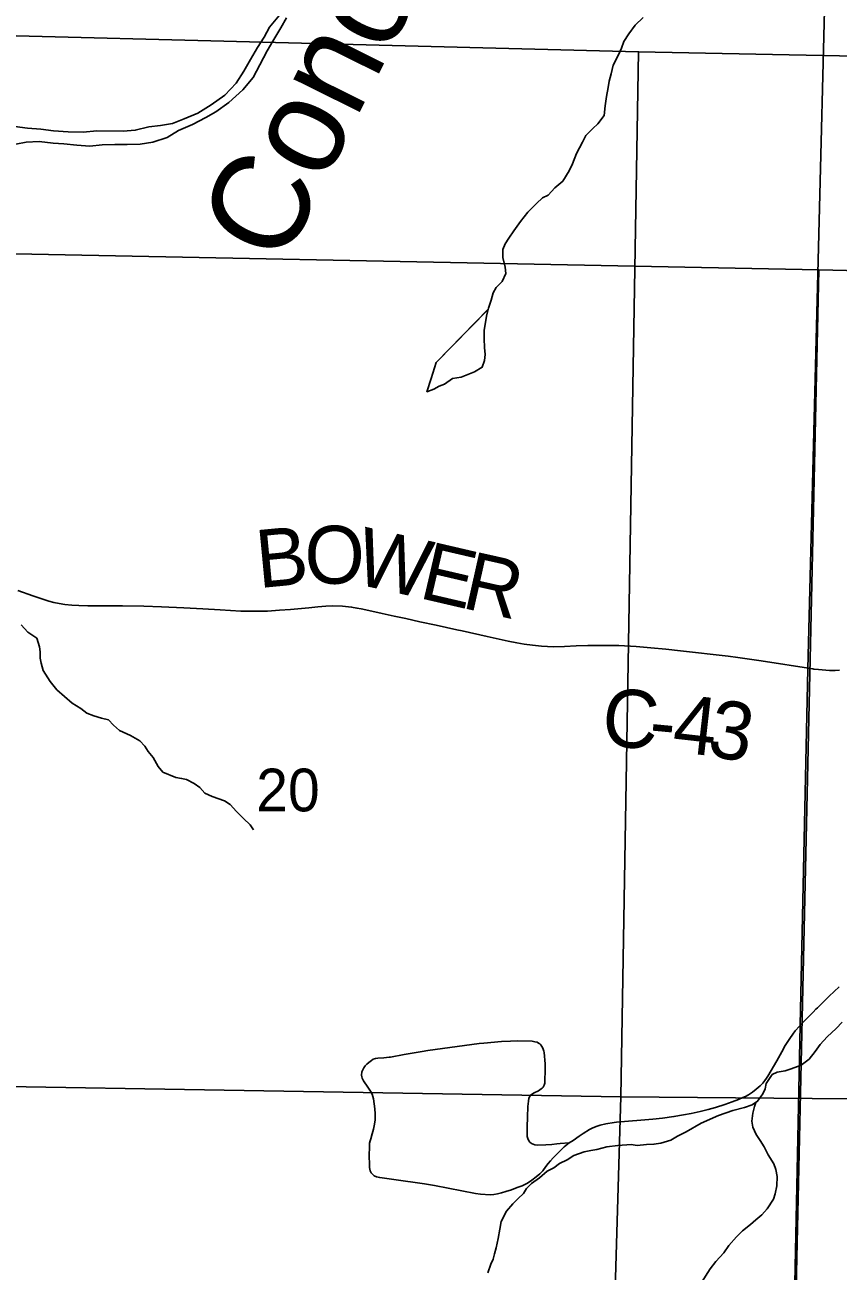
# Model space of a CAD drawing. Extents: x -19.9 to 41.9, y 0 to 32.3.
# Drawn here: x 6.268 to 7.065, y 15.733 to 16.956 of the extents above; entities that cross this region are included whole.
import ezdxf

# ---------------------------------------------------------------- set-up
doc = ezdxf.new("R2010")
doc.units = 0
for name, color, linetype in [('GM_X_Corporation', 7, 'Continuous'), ('GM_X_County_Road', 7, 'Continuous'), ('GM_X_County_Road_Text', 7, 'Continuous'), ('GM_X_Major_River', 7, 'Continuous'), ('GM_X_Major_River_Text', 7, 'Continuous'), ('GM_X_Minor_River', 7, 'Continuous'), ('GM_X_Section', 7, 'Continuous'), ('GM_X_Section_Text', 7, 'Continuous'), ('GM_X_Township', 7, 'Continuous'), ('GM_X_Township_Road', 7, 'Continuous')]:
    doc.layers.add(name, color=color, linetype=linetype)

msp = doc.modelspace()

# ---------------------------------------------------------------- linework, layer by layer
at = {"layer": 'GM_X_Corporation'}
for points in [[(5.8519, 16.9554), (6.8696, 16.9292), (6.8522, 15.9041), (5.8404, 15.9209)], [(6.8696, 16.9292), (7.8883, 16.9088), (7.8659, 15.8953), (6.8522, 15.9041)], [(6.8522, 15.9041), (6.8226, 14.894), (5.8188, 14.9036), (5.8404, 15.9209)], [(7.8659, 15.8953), (7.8436, 14.8739), (6.8226, 14.894), (6.8522, 15.9041)]]:
    msp.add_lwpolyline(points, close=True, dxfattribs=at)
at = {"layer": 'GM_X_County_Road'}
for points in [[(6.2608, 16.4008), (6.2755, 16.3954), (6.2842, 16.3925), (6.291, 16.3904), (6.296, 16.3891), (6.3011, 16.388), (6.3067, 16.3871), (6.3138, 16.3864), (6.3206, 16.386), (6.3294, 16.3858), (6.3635, 16.3857), (6.3843, 16.3852), (6.4018, 16.3847), (6.4235, 16.3838), (6.4421, 16.3829), (6.4593, 16.3819), (6.4796, 16.3806), (6.4853, 16.3804), (6.5055, 16.3806), (6.5175, 16.3813), (6.5282, 16.3821), (6.5463, 16.3838), (6.5549, 16.3847), (6.5628, 16.3853), (6.5691, 16.3856), (6.5792, 16.3854), (6.5822, 16.3851), (6.5881, 16.3844), (6.5934, 16.3834), (6.5976, 16.3826), (6.6078, 16.3804), (6.618, 16.3782), (6.6299, 16.3755), (6.6412, 16.3731), (6.655, 16.37), (6.6709, 16.3666), (6.6912, 16.3622), (6.6966, 16.361), (6.721, 16.3557), (6.7418, 16.3511), (6.7502, 16.3494), (6.7574, 16.3481), (6.7656, 16.347), (6.7744, 16.3461), (6.7802, 16.3457), (6.7859, 16.3456), (6.7969, 16.3459), (6.8083, 16.3463), (6.8199, 16.3467), (6.8295, 16.3469), (6.841, 16.3469), (6.8501, 16.3467), (6.8671, 16.3457), (6.8816, 16.3446), (6.8964, 16.3432), (6.9107, 16.3417), (6.9575, 16.3362), (6.967, 16.335), (6.9898, 16.3316), (7.0406, 16.3238), (7.0415, 16.3237)], [(7.0415, 16.3237), (7.046, 16.3232), (7.0569, 16.3224), (7.0624, 16.3223), (7.0667, 16.3225)]]:
    msp.add_lwpolyline(points, dxfattribs=at)
at = {"layer": 'GM_X_Major_River'}
for points in [[(6.5173, 16.9652), (6.5076, 16.9533), (6.5024, 16.9434), (6.4957, 16.9334), (6.489, 16.9216), (6.4823, 16.9101), (6.4748, 16.8983), (6.4636, 16.8867), (6.4504, 16.8771), (6.4372, 16.869), (6.424, 16.8635), (6.4123, 16.8588), (6.4005, 16.8568), (6.3891, 16.8555), (6.3759, 16.8523), (6.3641, 16.8514), (6.3383, 16.8518), (6.3247, 16.8502), (6.3102, 16.8507), (6.2958, 16.8517), (6.2832, 16.8534), (6.2703, 16.8544), (6.2578, 16.8558)], [(6.2587, 16.8387), (6.269, 16.8404), (6.2815, 16.8413), (6.2955, 16.8396), (6.3058, 16.8389), (6.3187, 16.8376), (6.3313, 16.8366), (6.3434, 16.8379), (6.3559, 16.8384), (6.3681, 16.8382), (6.3806, 16.8387), (6.3931, 16.8407), (6.4071, 16.8451), (6.4184, 16.852), (6.432, 16.8579), (6.4452, 16.8649), (6.455, 16.8703), (6.4678, 16.8796), (6.4814, 16.8919), (6.4915, 16.9041), (6.4981, 16.9164), (6.5052, 16.9301), (6.5108, 16.9397), (6.5186, 16.9527), (6.5242, 16.9626)]]:
    msp.add_lwpolyline(points, dxfattribs=at)
at = {"layer": 'GM_X_Minor_River'}
for points in [[(6.874, 16.9629), (6.8662, 16.9552), (6.8599, 16.9467), (6.8551, 16.9394), (6.8529, 16.9329), (6.8496, 16.9256), (6.8448, 16.916), (6.8427, 16.9076), (6.8409, 16.9003), (6.8398, 16.8942), (6.8381, 16.8854), (6.837, 16.8763), (6.8357, 16.8667), (6.8297, 16.8586), (6.8249, 16.854), (6.8178, 16.847), (6.8145, 16.8405), (6.8086, 16.8294), (6.8049, 16.8194), (6.8016, 16.8125), (6.7953, 16.8022), (6.7875, 16.7956), (6.7808, 16.7886), (6.7755, 16.7859), (6.7695, 16.7804), (6.7609, 16.7719), (6.7539, 16.7627), (6.7472, 16.7535), (6.7424, 16.7465), (6.7387, 16.7408), (6.7365, 16.7354), (6.7366, 16.7274), (6.7386, 16.7179), (6.7395, 16.7118), (6.7358, 16.7038), (6.7298, 16.698), (6.7269, 16.6926), (6.7251, 16.6857), (6.7225, 16.6777), (6.7204, 16.6697), (6.7183, 16.6559), (6.7181, 16.6475), (6.7186, 16.6392), (6.719, 16.6323), (6.7184, 16.6262), (6.7162, 16.6197), (6.7087, 16.6154), (6.6955, 16.6099), (6.6872, 16.6086), (6.6793, 16.6032), (6.674, 16.6012), (6.6688, 16.5981), (6.662, 16.5957), (6.666, 16.6087), (6.6711, 16.6244), (6.7218, 16.6762)], [(6.662, 16.5957), (6.6688, 16.5981), (6.674, 16.6012), (6.6793, 16.6032), (6.6872, 16.6086), (6.6955, 16.6099), (6.7087, 16.6154), (6.7162, 16.6197), (6.7184, 16.6262), (6.719, 16.6323), (6.7186, 16.6392), (6.7181, 16.6475), (6.7183, 16.6559), (6.7204, 16.6697), (6.7222, 16.6766)], [(6.7222, 16.6766), (6.6711, 16.6244), (6.666, 16.6087), (6.662, 16.5957)], [(6.264, 16.367), (6.2705, 16.3598), (6.2793, 16.3539), (6.2821, 16.3455), (6.2826, 16.3406), (6.2826, 16.3345), (6.2835, 16.3296), (6.2855, 16.3224), (6.2924, 16.3114), (6.299, 16.3032), (6.314, 16.2901), (6.3224, 16.2849), (6.3285, 16.2804), (6.3353, 16.2778), (6.3429, 16.2756), (6.3498, 16.2738), (6.3544, 16.2686), (6.3605, 16.2633), (6.3712, 16.2586), (6.3804, 16.2534), (6.3854, 16.2481), (6.3885, 16.2428), (6.3935, 16.2368), (6.3985, 16.2281), (6.4031, 16.2225), (6.4157, 16.2173), (6.4214, 16.2163), (6.4263, 16.2152), (6.4336, 16.2115), (6.4393, 16.2074), (6.4443, 16.2018), (6.4512, 16.1985), (6.4634, 16.1945), (6.4691, 16.1907), (6.4753, 16.184), (6.4822, 16.1772), (6.4887, 16.1709), (6.4918, 16.166)], [(7.0693, 15.9771), (7.0633, 15.9709), (7.0547, 15.9628), (7.0476, 15.9555), (7.0428, 15.9485), (7.0369, 15.9408), (7.029, 15.935), (7.0192, 15.9314), (7.0135, 15.9294), (7.0056, 15.9282), (7.0007, 15.9258), (6.9948, 15.917), (6.9937, 15.912), (6.9915, 15.907), (6.9863, 15.8997), (6.9811, 15.8962), (6.9736, 15.8934), (6.9622, 15.8906), (6.9479, 15.8858), (6.931, 15.8783), (6.9163, 15.8697), (6.9077, 15.8654), (6.9013, 15.8615), (6.8915, 15.8587), (6.8847, 15.8575), (6.8775, 15.8573), (6.8681, 15.8564), (6.8624, 15.8571), (6.8492, 15.8562), (6.8386, 15.8548), (6.8288, 15.8524), (6.8227, 15.8512), (6.8163, 15.8499), (6.8061, 15.8464), (6.7994, 15.8421), (6.7919, 15.8385), (6.7866, 15.8343), (6.7799, 15.8311), (6.7724, 15.8245), (6.7645, 15.8191), (6.7597, 15.8141), (6.7567, 15.8091), (6.7515, 15.8044), (6.7462, 15.799), (6.7399, 15.7917), (6.7348, 15.7817), (6.7334, 15.7741), (6.732, 15.7649), (6.7298, 15.7558), (6.7284, 15.75), (6.727, 15.7447), (6.7248, 15.7397), (6.7219, 15.7313)], [(6.9846, 15.8986), (6.9834, 15.8944), (6.9816, 15.8879), (6.9806, 15.8802), (6.9818, 15.8742), (6.9849, 15.867), (6.9888, 15.8613), (6.9927, 15.8549), (6.9966, 15.847), (7.0024, 15.8383), (7.0043, 15.8326), (7.0056, 15.8258), (7.0053, 15.8167), (7.0036, 15.809), (7.0021, 15.8037), (6.9958, 15.794), (6.9906, 15.7883), (6.9846, 15.7832), (6.9794, 15.7786), (6.9715, 15.7724), (6.9656, 15.7666), (6.9581, 15.7581), (6.9533, 15.7508), (6.9455, 15.7423), (6.9399, 15.7353), (6.9314, 15.7219)]]:
    msp.add_lwpolyline(points, dxfattribs=at)
at = {"layer": 'GM_X_Section'}
for points in [[(6.0276, 16.7357), (7.0463, 16.7153), (7.0239, 15.7019), (6.0103, 15.7106)], [(8.0651, 16.6907), (8.0435, 15.6754), (7.0239, 15.7019), (7.0463, 16.7153)]]:
    msp.add_lwpolyline(points, close=True, dxfattribs=at)
at = {"layer": 'GM_X_Township'}
for p, q in [((7.0592, 17.259), (7.0356, 16.3239)), ((7.0356, 16.3239), (7.0282, 15.9744)), ((7.0282, 15.9744), (7.012, 15.2123))]:
    msp.add_line(p, q, dxfattribs=at)
at = {"layer": 'GM_X_Township_Road'}
for points in [[(7.0436, 15.9899), (7.045, 15.9913), (7.0564, 16.0026), (7.0663, 16.012)], [(7.0309, 15.9771), (7.0368, 15.983), (7.0408, 15.9871), (7.0436, 15.9899)], [(6.7757, 15.8315), (6.7787, 15.8356), (6.781, 15.8386), (6.7833, 15.8412), (6.7858, 15.844), (6.7894, 15.8477), (6.794, 15.8523), (6.7967, 15.8549), (6.8016, 15.8588), (6.8053, 15.8612), (6.8114, 15.8655), (6.8153, 15.868), (6.8215, 15.8718), (6.8247, 15.8735), (6.8289, 15.8751), (6.832, 15.8761), (6.8375, 15.8774), (6.8458, 15.8787), (6.8479, 15.879), (6.8835, 15.8822), (6.8931, 15.8832), (6.9043, 15.8846), (6.9136, 15.8862), (6.9213, 15.8877), (6.93, 15.8896), (6.938, 15.8916), (6.9451, 15.8936), (6.9541, 15.8965), (6.9613, 15.899), (6.9675, 15.9013), (6.972, 15.9033), (6.9744, 15.9044), (6.9773, 15.9061), (6.9814, 15.9087), (6.985, 15.9115), (6.9889, 15.9149), (6.9915, 15.9175), (6.9935, 15.9199), (6.9952, 15.9223), (6.9965, 15.9243), (7.0051, 15.9392), (7.01, 15.948), (7.0135, 15.9542), (7.0181, 15.9613), (7.0209, 15.9654), (7.0232, 15.9688), (7.0273, 15.9734), (7.0309, 15.9771)], [(6.7757, 15.8315), (6.7727, 15.8284), (6.7691, 15.8255), (6.7649, 15.8223), (6.7606, 15.8193), (6.7553, 15.8168), (6.7505, 15.8149), (6.7449, 15.8128), (6.7393, 15.8111), (6.7351, 15.8097), (6.7311, 15.8088), (6.7275, 15.8081), (6.7241, 15.8078), (6.7147, 15.8085), (6.7098, 15.8092), (6.6695, 15.817), (6.6596, 15.8186), (6.6297, 15.8229), (6.6158, 15.8248), (6.6126, 15.8255), (6.6104, 15.8266), (6.6085, 15.828), (6.6073, 15.8294), (6.6063, 15.8313), (6.6061, 15.8329), (6.6058, 15.8347), (6.6056, 15.8388), (6.6055, 15.8447), (6.6056, 15.8565), (6.6058, 15.8586), (6.6063, 15.8609), (6.6069, 15.8628), (6.6083, 15.8677), (6.6097, 15.8723), (6.6106, 15.8771), (6.6112, 15.8814), (6.6113, 15.8872), (6.6109, 15.8921), (6.6095, 15.902), (6.6082, 15.9066), (6.6067, 15.9097), (6.6035, 15.9146), (6.6005, 15.9186), (6.5999, 15.9196), (6.5985, 15.9224), (6.5981, 15.9237), (6.5978, 15.9253), (6.5981, 15.9284), (6.5994, 15.9313), (6.6001, 15.9325), (6.6015, 15.9343), (6.603, 15.936), (6.605, 15.9378), (6.6076, 15.9398), (6.6094, 15.941), (6.6117, 15.9415), (6.614, 15.942), (6.6196, 15.9424), (6.6249, 15.9428), (6.6264, 15.943), (6.6396, 15.9454), (6.6574, 15.9486), (6.663, 15.9494), (6.7133, 15.9563), (6.7177, 15.9568), (6.7351, 15.9582), (6.7439, 15.9587), (6.7505, 15.9588), (6.7652, 15.9586), (6.7677, 15.9581), (6.77, 15.9575), (6.7716, 15.9567), (6.7727, 15.9559), (6.7736, 15.9551), (6.7748, 15.9535), (6.7758, 15.9516), (6.7767, 15.9489), (6.777, 15.9476), (6.7779, 15.9365), (6.7781, 15.9323), (6.7778, 15.9175), (6.7769, 15.9154), (6.7759, 15.9135), (6.7751, 15.9125), (6.7742, 15.9117), (6.7713, 15.91), (6.7671, 15.9079), (6.7636, 15.9057), (6.7621, 15.9027), (6.7615, 15.8997), (6.7609, 15.8944), (6.7606, 15.8842), (6.7603, 15.8746), (6.7602, 15.8689), (6.7602, 15.867), (6.7603, 15.8652), (6.7609, 15.8632), (6.762, 15.8609), (6.763, 15.8596), (6.7646, 15.8583), (6.7661, 15.8575), (6.768, 15.8568), (6.7702, 15.8565), (6.7787, 15.8568), (6.7845, 15.8574), (6.7893, 15.8579), (6.7928, 15.8581), (6.8016, 15.8588)]]:
    msp.add_lwpolyline(points, dxfattribs=at)

# ---------------------------------------------------------------- texts
at = {"layer": 'GM_X_County_Road_Text'}
for s, rotation, p in [('B', 5.445, (6.497, 16.403)), ('O', 0.1785, (6.542, 16.4073)), ('W', 347.5603, (6.5888, 16.4079)), ('E', 346.8836, (6.6529, 16.3937)), ('R', 347.3633, (6.6948, 16.384)), ('C', 354.9232, (6.8321, 16.2491)), ('4', 353.5334, (6.9015, 16.2428)), ('3', 350.4855, (6.9355, 16.2389)), ('-', 354.5978, (6.8785, 16.2449))]:
    msp.add_text(s, height=0.0568, rotation=rotation, dxfattribs=at).set_placement(p)
at = {"layer": 'GM_X_Major_River_Text'}
msp.add_text('Conotton', height=0.09472, rotation=63.5646, dxfattribs=at).set_placement((6.5202, 16.7172))
at = {"layer": 'GM_X_Section_Text'}
msp.add_text('20', height=0.04186, rotation=0, dxfattribs=at).set_placement((6.4946, 16.1841))

doc.saveas('drawing.dxf')
